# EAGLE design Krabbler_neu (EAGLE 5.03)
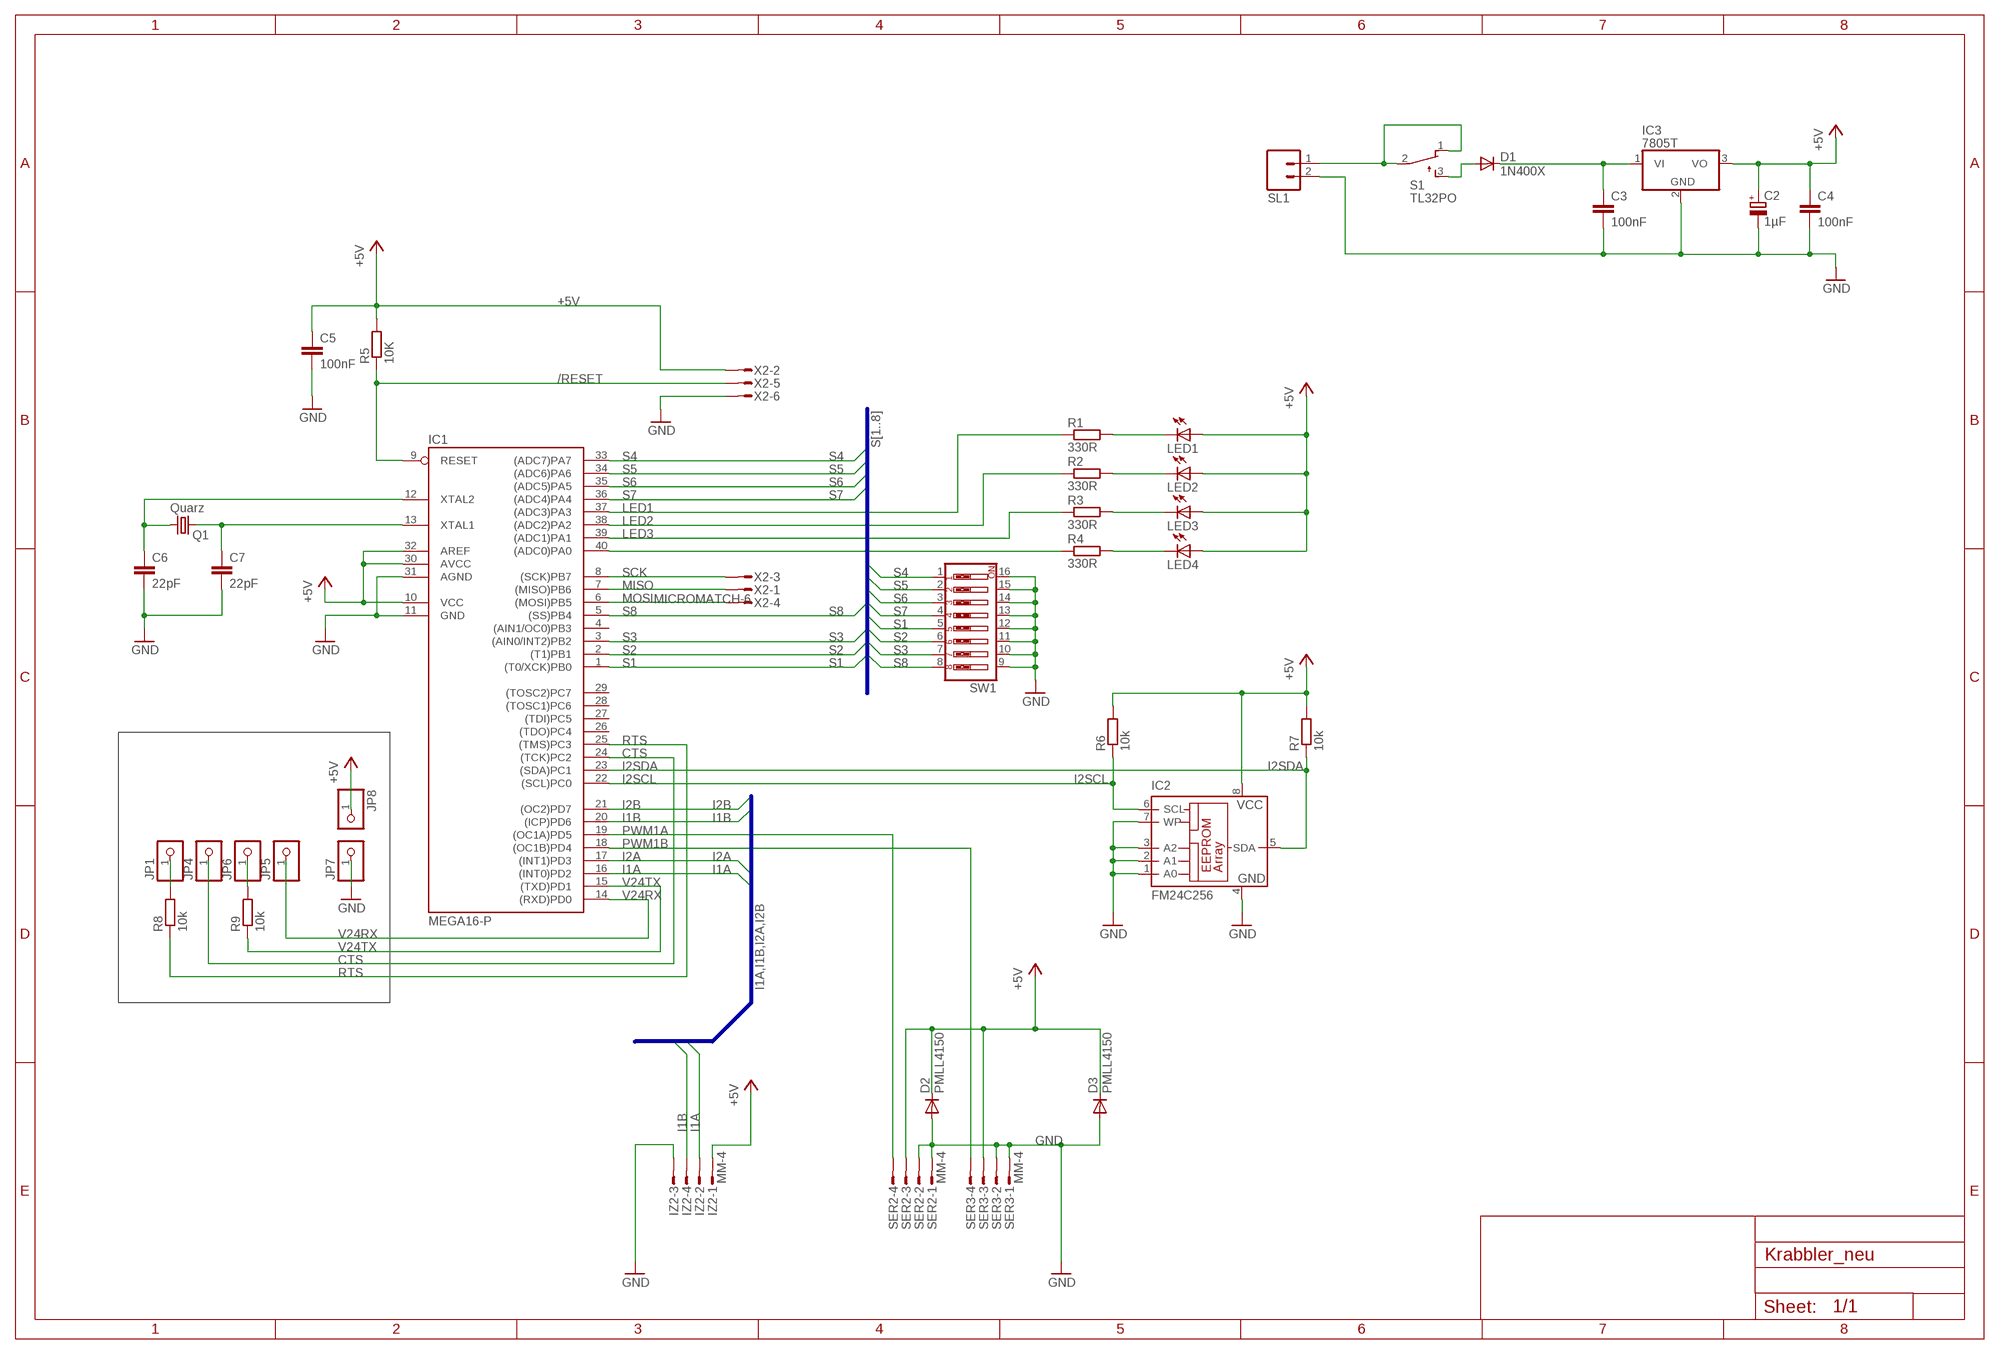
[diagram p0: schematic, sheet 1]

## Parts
C2  1µF  CPOL-EUE2.5-5  [E2,5-5]
C3  100nF  C-EUC0805  [C0805]
C4  100nF  C-EUC0805  [C0805]
C5  100nF  C-EUC0805  [C0805]
C6  22pF  C-EUC0805  [C0805]
C7  22pF  C-EUC0805  [C0805]
D1  1N400X  1N4004  [DO41-10]
D2  PMLL4150  [SOD80C]
D3  PMLL4150  [SOD80C]
IC1  MEGA16-P  [DIL40]
IC2  FM24C256  24LC256SN  [SO-08]
IC3  7805T  [TO220H]
IZ2  MM-4  MICROMATCH-4  [MICROMATCH-4]
JP1  PINHD-1X1  [1X01]
JP4  PINHD-1X1  [1X01]
JP5  PINHD-1X1  [1X01]
JP6  PINHD-1X1  [1X01]
JP7  PINHD-1X1  [1X01]
JP8  PINHD-1X1  [1X01]
LED1  grün  LED3MM  [LED3MM]
LED2  grün  LED3MM  [LED3MM]
LED3  grün  LED3MM  [LED3MM]
LED4  grün  LED3MM  [LED3MM]
Q1  Quarz  CRYSTALHC49S  [HC49/S]
R1  330R  R-EU_R1206  [R1206]
R2  330R  R-EU_R1206  [R1206]
R3  330R  R-EU_R1206  [R1206]
R4  330R  R-EU_R1206  [R1206]
R5  10K  R-EU_R1206  [R1206]
R6  10k  R-EU_R1206  [R1206]
R7  10k  R-EU_R1206  [R1206]
R8  10k  R-EU_R1206  [R1206]
R9  10k  R-EU_R1206  [R1206]
S1  TL32PO  [TL3XPO]
SER2  MM-4  MICROMATCH-4  [MICROMATCH-4]
SER3  MM-4  MICROMATCH-4  [MICROMATCH-4]
SL1  MA02  [02PA]
SW1  SW_DIP-8  [EDG-08]
X2  MICROMATCH-6  [MICROMATCH-6]

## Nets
+5V: C2.+ C4.1 C5.1 D2.C D3.C IC1.10(VCC) IC1.30(AVCC) IC1.32(AREF) IC2.8(VCC) IC3.3(VO) IZ2.1 JP8.1 LED1.A LED2.A LED3.A LED4.A R5.2 R6.2 R7.2 SER2.3 SER3.3 X2.2
/RESET: IC1.9(RESET) R5.1 X2.5
CTS: IC1.24((TCK)PC2) JP4.1
GND: C2.- C3.2 C4.2 C5.2 C6.2 C7.2 D2.A D3.A IC1.11(GND) IC1.31(AGND) IC2.1(A0) IC2.2(A1) IC2.3(A2) IC2.4(GND) IC2.7(WP) IC3.2(GND) IZ2.3 JP7.1 SER2.1 SER2.2 SER3.1 SER3.2 SL1.2 SW1.9 SW1.10 SW1.11 SW1.12 SW1.13 SW1.14 SW1.15 SW1.16 X2.6
I1A: IC1.16((INT0)PD2) IZ2.2
I1B: IC1.20((ICP)PD6) IZ2.4
I2A: IC1.17((INT1)PD3)
I2B: IC1.21((OC2)PD7)
I2SCL: IC1.22((SCL)PC0) IC2.6(SCL) R6.1
I2SDA: IC1.23((SDA)PC1) IC2.5(SDA) R7.1
LED1: IC1.37((ADC3)PA3) R1.1
LED2: IC1.38((ADC2)PA2) R2.1
LED3: IC1.39((ADC1)PA1) R3.1
MISO: IC1.7((MISO)PB6) X2.1
MOSI: IC1.6((MOSI)PB5) X2.4
N$1: LED1.K(C) R1.2
N$2: LED2.K(C) R2.2
N$4: LED3.K(C) R3.2
N$5: IC1.40((ADC0)PA0) R4.1
N$6: JP1.1 R8.2
N$7: JP6.1 R9.2
N$8: LED4.K(C) R4.2
N$9: S1.1(O) S1.2(P) SL1.1
N$10: D1.A S1.3(S)
N$18: C7.1 IC1.13(XTAL1) Q1.1
N$19: C6.1 IC1.12(XTAL2) Q1.2
N$22: C3.1 D1.C IC3.1(VI)
PWM1A: IC1.19((OC1A)PD5) SER2.4
PWM1B: IC1.18((OC1B)PD4) SER3.4
RTS: IC1.25((TMS)PC3) R8.1
S1: IC1.1((T0/XCK)PB0) SW1.5
S2: IC1.2((T1)PB1) SW1.6
S3: IC1.3((AIN0/INT2)PB2) SW1.7
S4: IC1.33((ADC7)PA7) SW1.1
S5: IC1.34((ADC6)PA6) SW1.2
S6: IC1.35((ADC5)PA5) SW1.3
S7: IC1.36((ADC4)PA4) SW1.4
S8: IC1.5((SS)PB4) SW1.8
SCK: IC1.8((SCK)PB7) X2.3
V24RX: IC1.14((RXD)PD0) JP5.1
V24TX: IC1.15((TXD)PD1) R9.1
Unconnected: IC1.4((AIN1/OC0)PB3) IC1.26((TDO)PC4) IC1.27((TDI)PC5) IC1.28((TOSC1)PC6) IC1.29((TOSC2)PC7)

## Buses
S[1..8]
I1A,I1B,I2A,I2B

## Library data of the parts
C2 = rcl:CPOL-EU: POLARIZED CAPACITOR, European symbol
C3-C7 = rcl:C-EU: CAPACITOR, European symbol
D1 = diode:1N4004: DIODE
D2 D3 = diode:PMLL4150: DIODE
IC1 = atmel:MEGA16-P: MICROCONTROLLER 16 Kbytes FLASH 1 kbytes SRAM 512 bytes EEPROM USART 8-channel 10 bit ADC Source: avr.lbr
IC2 = microchip:24*: Serial EEPROM I2C
IC3 = linear:78*: Positive VOLTAGE REGULATOR Source: http://cache.national.com/ds/LM/LM78L05.pdf http://www.fairchildsemi.com/ds/LM/LM7805.pdf
IZ2 SER2 SER3 = con-amp-micromatch:MICROMATCH-4: MicroMaTch 4 7-215464-4 / 0-215464-4 Drawing Number C-215464 DDEController.pdf
JP1 JP4-JP8 = pinhead:PINHD-1X1: PIN HEADER
LED1-LED4 = led:LED: LED
Q1 = crystal:CRYSTAL: CRYSTAL
R1-R9 = rcl:R-EU_: RESISTOR, European symbol
S1 = switch:TL32PO: TINY SWITCH ON - MOM Source: http://www2.produktinfo.conrad.com/datenblaetter/700000-724999/705152-da-01-de-Subminiaturschalter_TL_36YO.pdf
SL1 = con-amp-quick:MA02: AMP QUICK CONNECTOR
SW1 = special:SW_DIP-8: DIP SWITCH
X2 = con-amp-micromatch:MICROMATCH-6: MicroMaTch 6 7-215464-6 / 0-215464-6 Drawing Number C-215464 DDEController.pdf

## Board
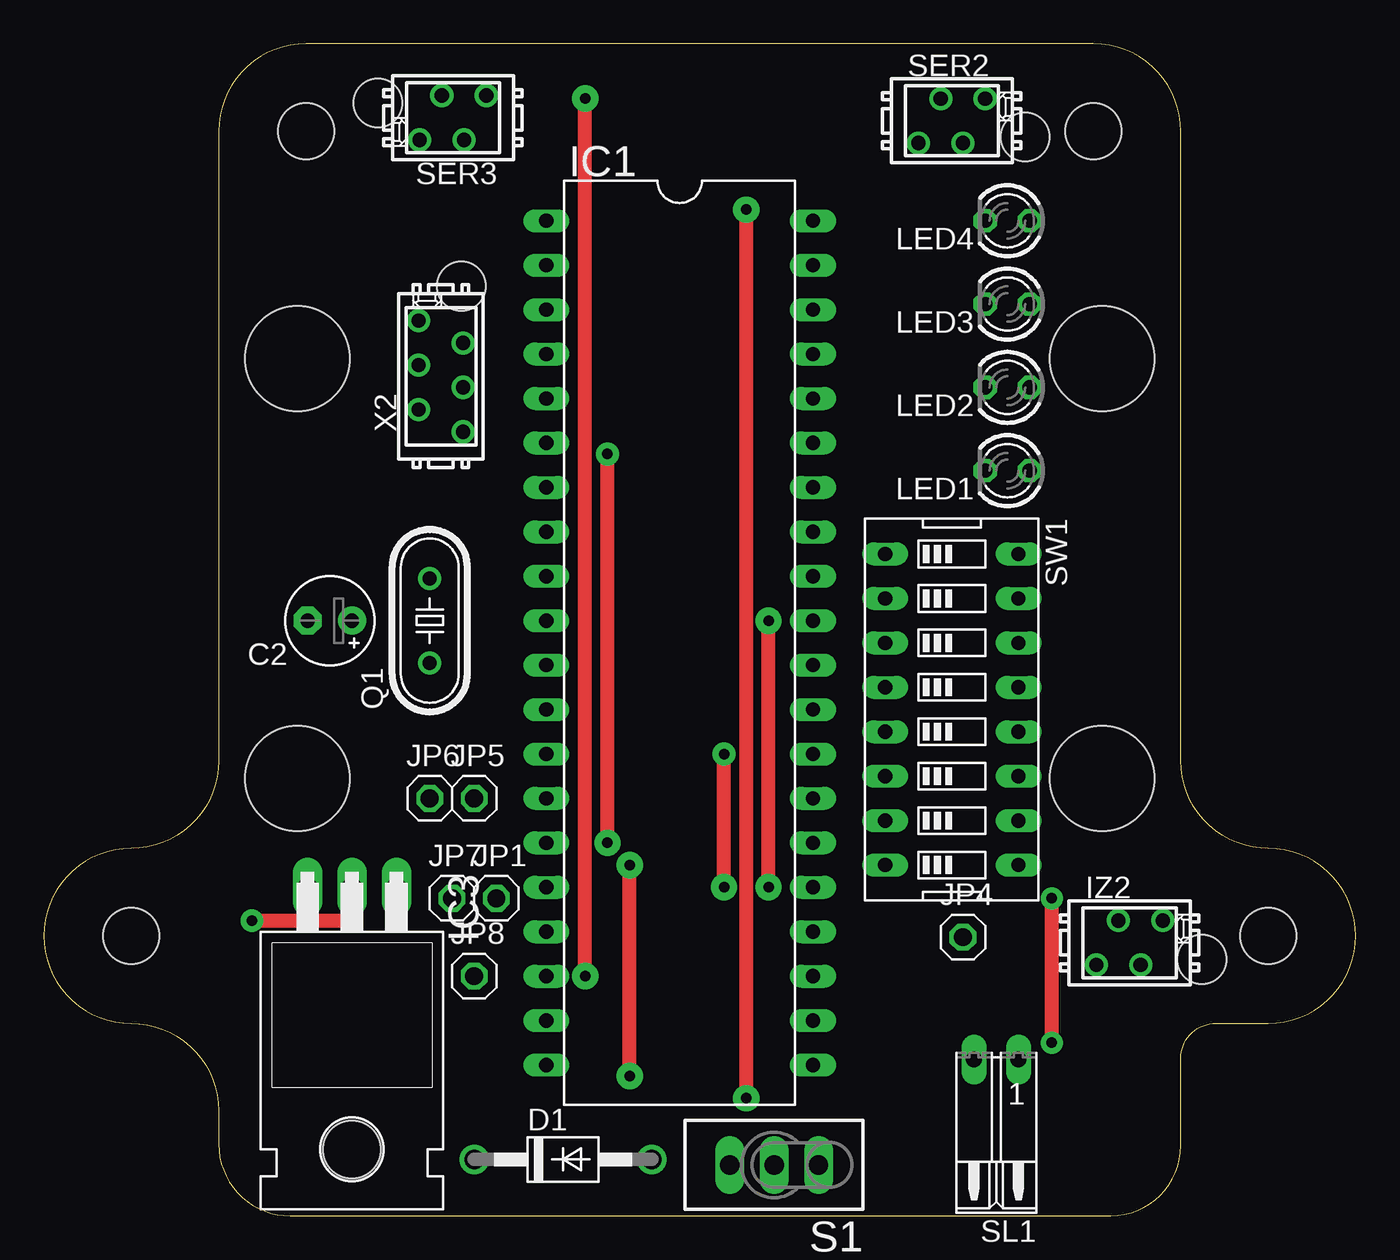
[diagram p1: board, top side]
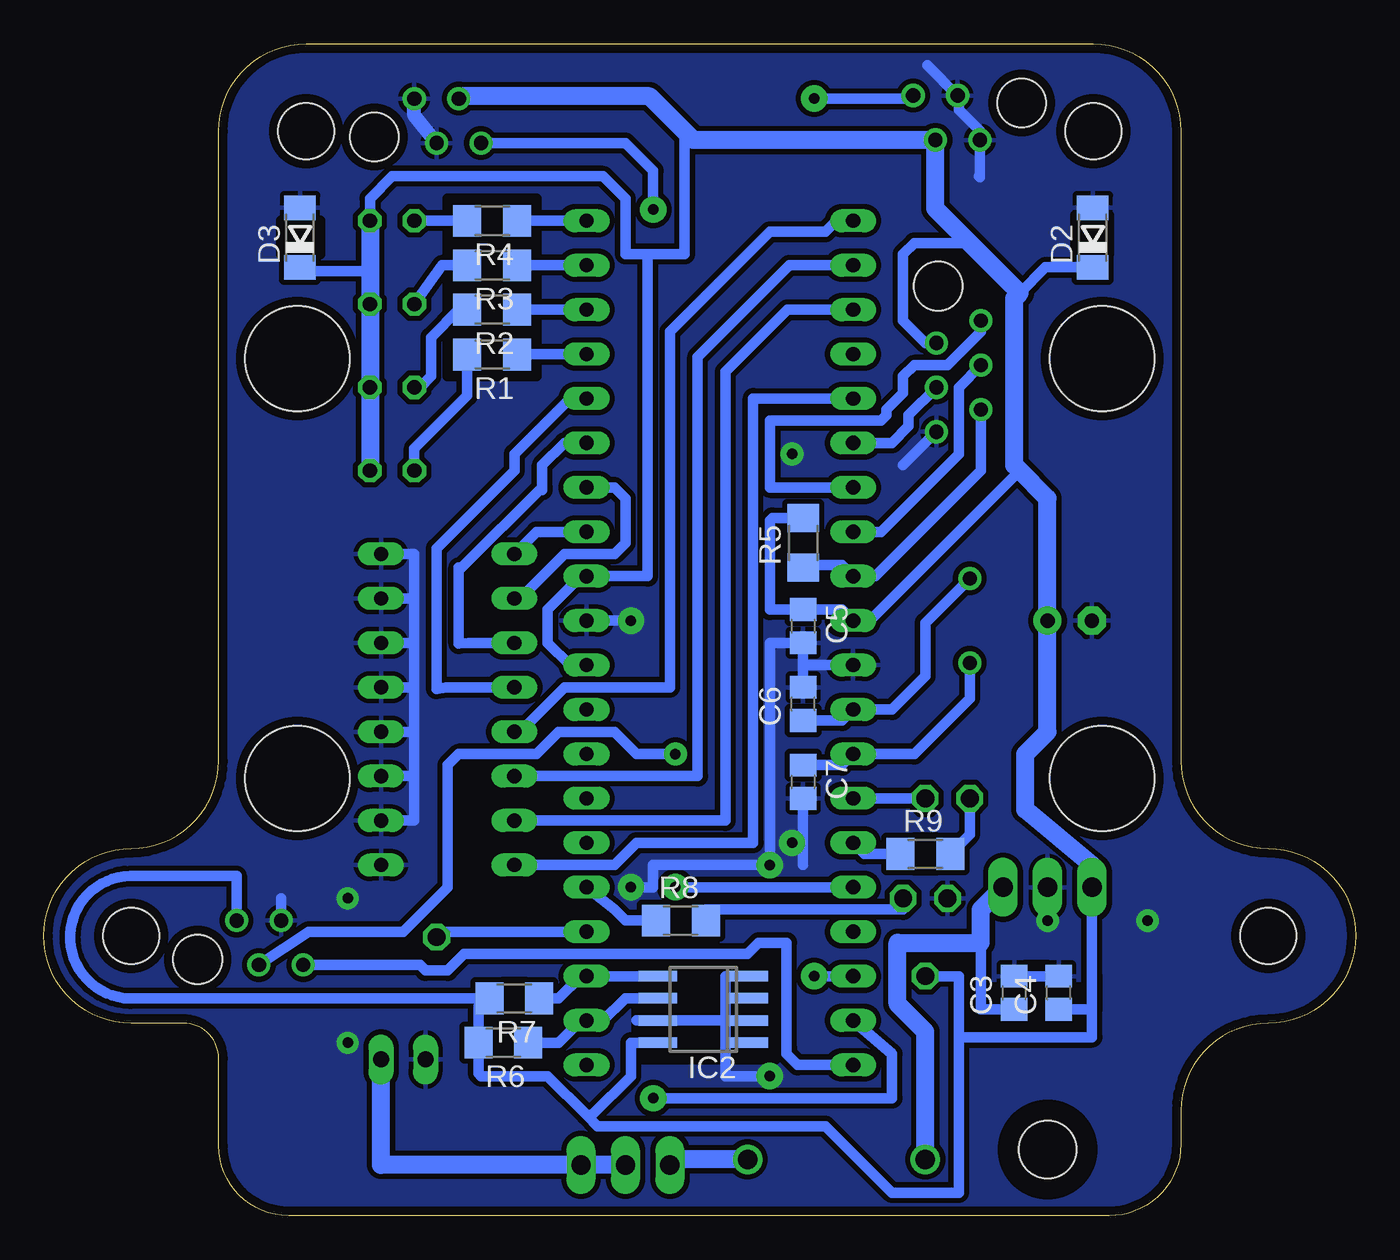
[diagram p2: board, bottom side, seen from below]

Size 75 x 67 mm. Coordinates in mm from the lower left corner, seen from the top.
Outline: 65,62 arc90 60,67 15,67 arc90 10,62 10,26 arc-90 5,21 arc90 0,16 arc90 5,11 arc-90 10,6 10,4.1 arc90 14.1,0 61,0 arc90 65,4 65,9 arc-90 67,11 70,11 arc90 75,16 arc90 70,21 arc-90 65,26 65,62
Copper layers (1*16): Top 0.035mm / dielectric 1.5mm / Bottom 0.035mm
Design rules "default *": minimum track width 10mil, minimum drill 24mil, track to track 8mil, track to pad 8mil, pad to pad 8mil, via to via 8mil, smd to smd 8mil, copper to edge 20mil, drill to drill 8mil, minimum pad ring 10mil, minimum via ring 8mil, stop-mask expansion 4mil, vias tented up to drill 0mil, thermal gap 10mil
Holes 6 mm at 14.5,25 14.5,49 60.5,25 60.5,49
Holes 3.2 mm at 5,16 70,16 60,62 15,62
Holes 2.8 mm at 66.2,14.65 19.1,63.62 56.1,61.67 23.87,53.14
bRestrict: area 17.6,12.4 to 18.9,14.3; area 37.9,15.9 to 39.2,17.8; area 24,19.7 to 25.2,21.6; area 15.7,11.8 to 17.6,13.1; area 18.9,11.8 to 20.8,13.1; area 47.5,11.5 to 48.7,13.4; area 48.1,8.9 to 49.4,10.8; area 33.2,8.9 to 41.1,15; area 36.7,15 to 38.6,16.2; area 30.6,37.8 to 32.5,39.1; area 46.8,48 to 51.9,58.1; area 59.2,55 to 61.4,56.9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

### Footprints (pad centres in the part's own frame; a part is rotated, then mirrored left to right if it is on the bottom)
E2,5-5 = drill 0.813 pad 1.6 round: + -1.27,0 | drill 0.813 pad 1.6 octagon: - 1.27,0
C0805 = smd 1.3 x 1.5: 1 -0.95,0; 2 0.95,0
DO41-10 = drill 1.118 round: A 5.08,0; C -5.08,0
SOD80C = smd 1.4 x 1.8: A 1.7,0; C -1.7,0
DIL40 = drill 0.813 long: 1 -24.13,-7.62; 2 -21.59,-7.62; 3 -19.05,-7.62; 4 -16.51,-7.62; 5 -13.97,-7.62; 6 -11.43,-7.62; 7 -8.89,-7.62; 8 -6.35,-7.62; 9 -3.81,-7.62; 10 -1.27,-7.62; 11 1.27,-7.62; 12 3.81,-7.62; 13 6.35,-7.62; 14 8.89,-7.62; 15 11.43,-7.62; 16 13.97,-7.62; 17 16.51,-7.62; 18 19.05,-7.62; 19 21.59,-7.62; 20 24.13,-7.62; 21 24.13,7.62; 22 21.59,7.62; 23 19.05,7.62; 24 16.51,7.62; 25 13.97,7.62; 26 11.43,7.62; 27 8.89,7.62; 28 6.35,7.62; 29 3.81,7.62; 30 1.27,7.62; 31 -1.27,7.62; 32 -3.81,7.62; 33 -6.35,7.62; 34 -8.89,7.62; 35 -11.43,7.62; 36 -13.97,7.62; 37 -16.51,7.62; 38 -19.05,7.62; 39 -21.59,7.62; 40 -24.13,7.62
SO-08 = smd 0.6 x 2.2: 1 -1.905,-2.6; 2 -0.635,-2.6; 3 0.635,-2.6; 4 1.905,-2.6; 5 1.905,2.6; 6 0.635,2.6; 7 -0.635,2.6; 8 -1.905,2.6
TO220H = drill 1.118 long: 1 -2.54,-10.16; 2 0,-10.16; 3 2.54,-10.16 | hole 3.302: 0,4.826
MICROMATCH-4 = drill 0.813 round: 1 1.905,1.27; 2 0.635,-1.27; 3 -0.635,1.27; 4 -1.905,-1.27
1X01 = drill 1.016 octagon: 1 0,0
LED3MM = drill 0.813 octagon: A -1.27,0; K 1.27,0
HC49/S = drill 0.813 round: 1 -2.413,0; 2 2.413,0
R1206 = smd 1.6 x 1.803: 1 -1.422,0; 2 1.422,0
TL3XPO = drill 1.1 pad 1.422 long: 1 -2.54,0; 2 0,0; 3 2.54,0
02PA = drill 0.914 long: 1 -1.27,0; 2 1.27,0
EDG-08 = drill 0.813 long: 1 -8.89,-3.81; 2 -6.35,-3.81; 3 -3.81,-3.81; 4 -1.27,-3.81; 5 1.27,-3.81; 6 3.81,-3.81; 7 6.35,-3.81; 8 8.89,-3.81; 9 8.89,3.81; 10 6.35,3.81; 11 3.81,3.81; 12 1.27,3.81; 13 -1.27,3.81; 14 -3.81,3.81; 15 -6.35,3.81; 16 -8.89,3.81
MICROMATCH-6 = drill 0.813 round: 1 3.175,1.27; 2 1.905,-1.27; 3 0.635,1.27; 4 -0.635,-1.27; 5 -1.905,1.27; 6 -3.175,-1.27

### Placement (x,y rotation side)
C2  16.35,34.02 180 top
C3  19.52,12.75 90 bottom
C4  16.98,12.75 90 bottom
C5  31.59,33.7 270 bottom
C6  31.59,29.26 90 bottom
C7  31.59,24.81 270 bottom
D1  29.68,3.22 0 top
D2  15.04,55.92 90 bottom
D3  60.35,55.92 90 bottom
IC1  36.35,32.75 270 top
IC2  37.3,11.79 90 bottom
IC3  17.62,8.62 180 top
IZ2  62.07,15.61 0 top
JP1  25.88,18.14 0 top
JP4  52.55,15.92 0 top
JP5  24.61,23.86 0 top
JP6  22.06,23.86 0 top
JP7  23.34,18.14 0 top
JP8  24.61,13.7 0 top
LED1  55.09,42.59 180 top
LED2  55.09,47.35 180 top
LED3  55.09,52.12 180 top
LED4  55.09,56.88 180 top
Q1  22.06,34.02 90 top
R1  49.38,49.23 180 bottom
R2  49.37,51.8 180 bottom
R3  49.37,54.34 180 bottom
R4  49.37,56.88 180 bottom
R5  31.59,38.47 90 bottom
R6  48.73,9.89 180 bottom
R7  48.1,12.43 180 bottom
R8  38.58,16.88 0 bottom
R9  24.61,20.68 0 bottom
S1  41.75,2.91 180 top
SER2  51.91,62.59 0 top
SER3  23.39,62.77 180 top
SL1  54.45,8.94 180 top
SW1  51.91,28.94 270 top
X2  22.7,47.99 90 top

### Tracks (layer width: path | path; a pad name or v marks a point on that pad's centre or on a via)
+5V
  Bottom 0.61: IC2.8 41.43,9.89 41.43,7.99 43.66,5.76 43.97,5.76 | LED4.A 56.35,58.15 55.09,59.42 43.02,59.42 41.75,58.15 41.75,54.98 40.48,54.98 | 40.48,54.98 38.36,54.98 38.36,62 | 51.09,64 SER2.3 | D3.C 60.13,54 56.35,54 | X2.2 24.61,49.9 25.88,51.16 25.88,54.98 25.24,55.61 22.06,55.61 | R5.2 33.34,39.89 33.5,39.73 33.5,34.66 C5.1 29.36,34.65 IC1.10 27.78,34.02 19.21,42.59 | 40.48,54.98 40.48,36.56 IC1.32 44.29,36.56 46.2,34.66 46.2,32.75 44.92,31.48 IC1.30 | 43.97,5.76 43.34,5.13 30.32,5.13 26.51,1.32 22.7,1.32 22.7,10.21 | 43.97,5.76 46.2,7.99 50.01,7.99 50.16,8.14 R6.2 50.16,11.79 arc90 R7.2 | R7.2 49.37,12.43 | 15.08,13.7 15.08,10.21 22.7,10.21 | 15.08,13.7 IC3.3 | C4.1 15.08,11.8 15.08,13.7 | 22.7,10.21 22.7,13.7 JP8.1 | IZ2.1 63.98,19.41 69.69,19.41 arc-190 69.69,12.43 R7.2 | 19.21,52.75 17.74,54.22 D2.C
  Bottom 1.016: LED1.A LED2.A LED3.A 56.35,54 LED4.A | 51.09,64 40.36,64 38.36,62 37.86,61.5 SER3.3 24.03,57.58 22.06,55.61 19.21,52.75 19.52,52.44 19.52,42.91 19.21,42.59 17.62,41.01 C2.+ 17.62,27.67 18.89,26.4 18.89,23.23 15.08,20.05 IC3.3
/RESET
  Bottom 0.61: R5.1 31.59,37.2 29.37,37.2 IC1.9 27.46,36.56 21.43,42.59 X2.5
CTS
  Bottom 0.61: JP4.1 51.91,16.24 IC1.24
GND  (via drill 0.6 pad 1.27, 0.6 pad 1.3, 0.6 pad 1.5)
  Top 0.813: v32.23,21.32 v32.23,43.55 | v41.43,18.78 v41.43,34.02 | v33.5,7.99 v33.5,20.05 | v57.62,9.89 v57.62,18.14 | v11.9,16.88 v17.62,16.88
  Bottom 0.61: 36.03,11.16 IC2.7 41.11,11.16 | SW1.10 53.81,22.59 53.81,25.13 | 53.81,25.13 53.81,27.67 | 53.81,27.67 53.81,30.21 | 53.81,30.21 53.81,32.75 | 53.81,32.75 53.81,35.29 | 53.81,35.29 53.81,37.83 SW1.16 | 53.81,25.13 SW1.11 | 53.81,27.67 SW1.12 | 53.81,30.21 SW1.13 | 53.81,32.75 SW1.14 | 53.81,35.29 SW1.15 | 36.03,9.89 IC2.1 | 36.03,9.89 36.03,11.16 | 36.03,11.16 IC2.2 | 36.03,11.16 36.03,12.43 | 36.03,12.43 IC2.3 | 36.03,12.43 36.03,13.7 IC2.4 | 31.59,31.48 C6.2 | 31.59,31.48 C5.2 33.49,32.75 33.5,32.75 v33.5,20.05 40.16,20.05 40.16,18.78 v41.43,18.78 | 31.59,31.48 IC1.11 | D3.A 60.62,57.62 | X2.6 25.88,42.91 | C7.2 31.59,20.05 | 24.49,65.77 SER3.2 22.7,63.98 22.7,63.23 21.49,62.02 SER3.1 21.49,59.36 21.55,59.42 | SER2.1 53.81,64.23 | C4.2 C3.2 | v41.43,34.02 IC1.31 | v33.5,7.99 36.03,7.99 36.03,9.89 | IZ2.3 61.44,18.14
  Bottom 0.813: SER2.1 53.81,62.91 SER2.2
  Bottom 1.016: v17.62,16.88 IC3.2
  pour Bottom (isolate 0.3): -0.16,67.04 74.77,67.04 74.77,-0.27 -0.16,-0.27
  pour Bottom (isolate 0.4): -0.16,67.04 74.77,67.04 74.77,-0.27 -0.16,-0.27
I1A  (via drill 0.6 pad 1.3, 0.6 pad 1.5)
  Top 0.813: v38.89,18.78 v38.89,26.4
  Bottom 0.61: IC1.16 v38.89,18.78 | v38.89,26.4 41.11,26.4 42.38,27.67 45.56,27.67 46.83,26.4 51.27,26.4 51.91,25.77 51.91,18.78 54.45,16.24 59.85,16.24 IZ2.2
I1B
  Bottom 0.61: IC1.20 31.91,8.62 32.54,9.26 | 32.54,9.26 32.54,9.57 | 32.54,9.26 32.54,15.61 34.13,15.61 34.77,14.97 50.96,14.97 51.91,14.02 53.18,14.02 53.5,14.34 IZ2.4
I2SCL
  Bottom 0.61: IC2.6 41.75,12.43 43.02,11.16 IC1.22 44.29,11.16 45.56,9.89 R6.1
I2SDA
  Bottom 0.61: IC2.5 IC1.23 44.29,13.7 45.56,12.43 R7.1
LED1
  Bottom 0.61: R1.1 47.92,49.26 IC1.37
LED2
  Bottom 0.61: IC1.38 R2.1
LED3
  Bottom 0.61: IC1.39 R3.1
MISO
  Bottom 0.61: X2.1 21.43,50.53 23.34,48.62 25.24,48.62 25.88,47.99 25.88,47.04 26.83,46.09 26.83,45.77 27.14,45.45 33.5,45.45 33.5,41.64 IC1.7
MOSI
  Bottom 0.61: IC1.6 26.51,44.18 25.56,45.13 25.56,45.77 X2.4
N$1
  Bottom 0.61: LED1.K 53.81,43.86 50.8,46.88 R1.2
N$2
  Bottom 0.61: R2.2 51.27,51.8 52.86,50.21 52.86,47.99 53.5,47.35 LED2.K
N$4
  Bottom 0.61: LED3.K 52.23,54.34 R3.2
N$5
  Bottom 0.61: IC1.40 R4.1
N$6
  Bottom 0.61: R8.2 37.15,17.51 25.88,17.51 JP1.1
N$7
  Bottom 0.61: R9.2 22.06,21.8 JP6.1
N$8
  Bottom 0.61: R4.2 LED4.K
N$9
  Bottom 1.016: S1.1 44.29,2.27 | S1.2 S1.1 | SL1.1 55.72,2.91 S1.1
N$10
  Bottom 1.016: S1.3 39.21,3.22 D1.A
N$18
  Bottom 0.61: C7.1 29.37,25.76 IC1.13 25.24,26.4 22.06,29.57 Q1.1
N$19
  Bottom 0.61: C6.1 29.36,28.31 IC1.12 26.51,28.94 24.61,30.84 24.61,33.89 Q1.2
N$22
  Bottom 0.61: C3.1 21.43,11.8 21.43,15.61
  Bottom 1.016: IC3.1 21.43,17.51 21.43,15.61 26.19,15.61 26.19,12.11 24.61,10.53 D1.C
PWM1A  (via drill 0.6 pad 1.5)
  Top 0.813: v40.16,6.71 v40.16,57.52
  Bottom 0.61: IC1.19 26.51,9.26 26.51,6.71 v40.16,6.71 | SER2.4 41.75,61.33 40.16,59.74 v40.16,57.52
PWM1B  (via drill 0.6 pad 1.5)
  Top 0.813: v30.95,13.7 v30.95,63.87
  Bottom 0.61: SER3.4 25.79,63.87 v30.95,63.87 | IC1.18 v30.95,13.7
RTS
  Bottom 0.61: IC1.25 42.38,17.51 41.75,16.88 R8.1
S1
  Bottom 0.61: IC1.1 29.68,56.88 30.32,56.24 33.5,56.24 39.21,50.53 39.21,30.21 45.24,30.21 47.78,27.67 SW1.5
S2
  Bottom 0.61: IC1.2 32.38,54.34 37.62,49.09 37.62,25.13 SW1.6
S3
  Bottom 0.61: IC1.3 32.49,51.8 36.03,48.26 36.03,22.59 SW1.7
S4
  Bottom 0.61: IC1.33 46.83,39.1 SW1.1
S5
  Bottom 0.61: SW1.2 47.78,35.29 45.24,37.83 42.38,37.83 41.75,38.47 41.75,41.01 42.38,41.64 IC1.34
S6
  Bottom 0.61: SW1.3 50.69,32.75 51.27,32.7 51.27,37.05 51.1,37.05 46.51,41.64 | 46.51,41.64 46.51,41.49 | 46.51,41.64 46.51,42.91 45.24,44.18 IC1.35
S7
  Bottom 0.61: SW1.4 52,30.21 52.55,30.12 52.55,38.15 48.1,42.59 48.1,43.55 44.92,46.72 IC1.36
S8
  Bottom 0.61: IC1.5 34.45,46.72 34.45,21.32 41.11,21.32 42.38,20.05 SW1.8
SCK
  Bottom 0.61: X2.3 22.7,47.35 22.7,43.55 27.14,39.1 IC1.8
V24RX
  Bottom 0.61: JP5.1 IC1.14
V24TX
  Bottom 0.61: IC1.15 28.1,20.68 R9.1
